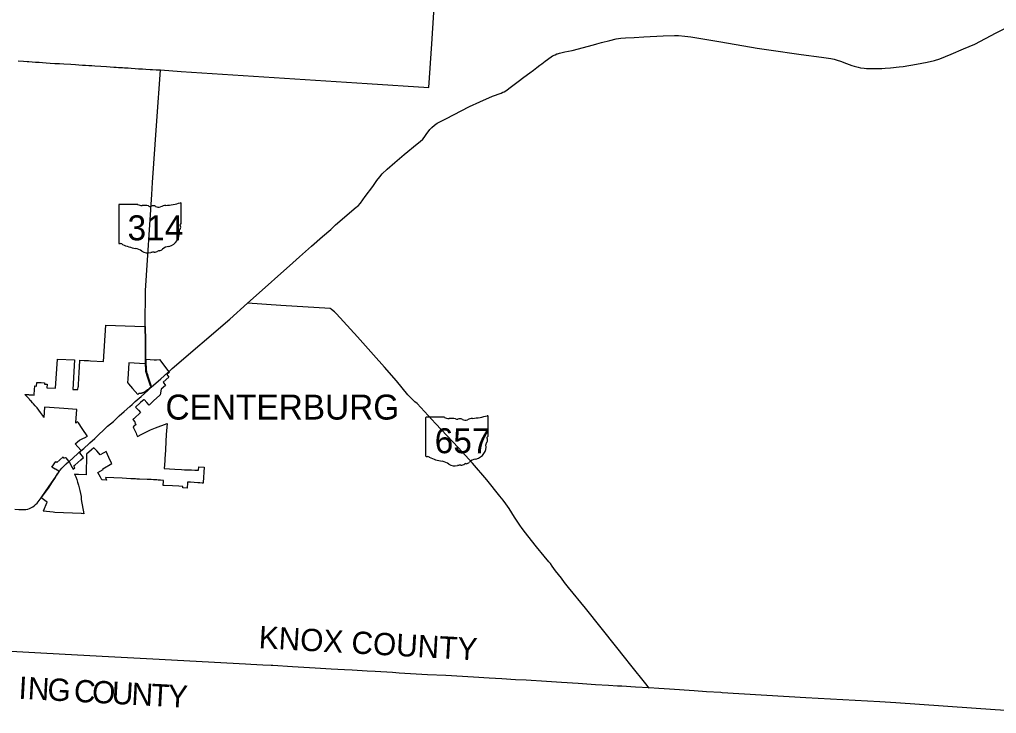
# Model space of a CAD drawing. Extents: x 1851937 to 2123937, y 789467 to 965467.
# Drawn here: x 1909296 to 1953112, y 826095 to 857229 of the extents above; entities that cross this region are included whole.
import ezdxf

# ---------------------------------------------------------------- set-up
doc = ezdxf.new("R2010")
doc.units = 0
for name, color, linetype in [('GM_X_Corporation', 7, 'Continuous'), ('GM_X_Corporation_Text', 7, 'Continuous'), ('GM_X_County', 7, 'Continuous'), ('GM_X_County_Text', 7, 'Continuous'), ('GM_X_State_Location', 7, 'Continuous'), ('GM_X_State_Route', 7, 'Continuous'), ('GM_X_State_Shield', 7, 'Continuous'), ('GM_X_US_Location', 7, 'Continuous'), ('GM_X_US_Route', 7, 'Continuous')]:
    doc.layers.add(name, color=color, linetype=linetype)

msp = doc.modelspace()

# ---------------------------------------------------------------- linework, layer by layer
at = {"layer": 'GM_X_Corporation'}
msp.add_lwpolyline([(1914951, 841986), (1914953, 841784), (1914954, 841776), (1914917, 841779), (1914202, 841823), (1914152, 841092), (1914142, 840939), (1914176, 840882), (1914362, 840675), (1914601, 840409), (1914651, 840452), (1914664, 840462), (1914665, 840463), (1914676, 840463), (1914689, 840463), (1914700, 840463), (1914710, 840463), (1914719, 840464), (1914728, 840464), (1914736, 840465), (1914743, 840467), (1914752, 840469), (1914760, 840471), (1914770, 840474), (1914778, 840477), (1914786, 840479), (1914793, 840482), (1914800, 840485), (1914807, 840488), (1914814, 840491), (1914821, 840494), (1914828, 840496), (1914836, 840497), (1914843, 840498), (1914852, 840500), (1914860, 840502), (1914867, 840504), (1914873, 840507), (1914879, 840509), (1914885, 840512), (1914891, 840515), (1914897, 840518), (1914903, 840521), (1914909, 840525), (1914915, 840530), (1914921, 840534), (1914928, 840539), (1914935, 840544), (1914941, 840548), (1914947, 840552), (1914953, 840555), (1914958, 840559), (1914962, 840562), (1914967, 840566), (1914972, 840570), (1914977, 840575), (1914983, 840580), (1914988, 840585), (1914992, 840590), (1914996, 840594), (1915000, 840598), (1915005, 840601), (1915013, 840607), (1915017, 840609), (1915021, 840612), (1915023, 840616), (1915027, 840620), (1915037, 840627), (1915045, 840631), (1915051, 840633), (1915059, 840633), (1915065, 840633), (1915068, 840633), (1915115, 840675), (1915160, 840716), (1915185, 840738), (1915209, 840760), (1915166, 840898), (1915150, 840948), (1915135, 840994), (1915078, 841176), (1915029, 841332), (1915009, 841396), (1914998, 841441), (1914991, 841478), (1914988, 841520), (1914985, 841602), (1914984, 841617), (1914977, 841775), (1914977, 841984), (1915331, 841967), (1915441, 841961), (1915573, 841981), (1915764, 841726), (1915976, 841444), (1915994, 841420), (1916012, 841396), (1915904, 841300), (1915991, 841191), (1915737, 840957), (1915837, 840814), (1915651, 840646), (1915606, 840395), (1915605, 840394), (1915584, 840375), (1915306, 840116), (1915109, 839931), (1915000, 840050), (1914882, 840178), (1914866, 840164), (1914814, 840118), (1914728, 840044), (1914708, 840025), (1914504, 839842), (1914591, 839745), (1914629, 839704), (1914728, 839594), (1914431, 839334), (1914414, 839319), (1914381, 839290), (1914460, 839185), (1914486, 839150), (1914460, 839126), (1914522, 839058), (1914396, 838950), (1914413, 838914), (1914438, 838857), (1914466, 838796), (1914493, 838736), (1914498, 838725), (1914520, 838676), (1914547, 838616), (1914574, 838556), (1914587, 838526), (1914775, 838623), (1915169, 838827), (1915400, 838912), (1915915, 839102), (1915875, 838607), (1915871, 838557), (1915868, 838507), (1915864, 838403), (1915859, 838303), (1915853, 838163), (1915849, 838063), (1915845, 837963), (1915843, 837938), (1915839, 837863), (1915832, 837763), (1915826, 837664), (1915819, 837564), (1915811, 837444), (1915799, 837256), (1915788, 837079), (1916262, 837054), (1916564, 837038), (1916699, 837031), (1916768, 837029), (1916786, 837028), (1917007, 837021), (1917163, 837017), (1917329, 837012), (1917339, 837164), (1917576, 837147), (1917535, 836462), (1917533, 836434), (1917533, 836432), (1917485, 836435), (1917383, 836442), (1917292, 836447), (1917127, 836459), (1916971, 836469), (1916871, 836475), (1916853, 836476), (1916831, 836477), (1916829, 836448), (1916817, 836208), (1916618, 836219), (1916621, 836279), (1916436, 836289), (1916152, 836306), (1915789, 836327), (1915744, 836329), (1915756, 836518), (1915758, 836548), (1915752, 836549), (1915613, 836558), (1915533, 836564), (1915508, 836566), (1915456, 836570), (1915403, 836573), (1915298, 836581), (1915194, 836588), (1915044, 836599), (1915048, 836587), (1915019, 836588), (1914669, 836608), (1914557, 836614), (1914504, 836617), (1914303, 836628), (1914291, 836628), (1913899, 836648), (1913157, 836686), (1913197, 836559), (1913008, 836577), (1912984, 836579), (1912926, 836697), (1912807, 836903), (1913047, 837039), (1913034, 837077), (1913429, 837312), (1913430, 837312), (1913366, 837448), (1913179, 837844), (1913071, 837788), (1912911, 837704), (1912849, 837772), (1912846, 837775), (1912758, 837872), (1912704, 837931), (1912630, 838012), (1912528, 837926), (1912296, 837729), (1912287, 836796), (1911938, 836816), (1911835, 836822), (1911795, 836824), (1911765, 836826), (1911815, 836708), (1911861, 836588), (1911902, 836467), (1911940, 836344), (1911974, 836221), (1912004, 836096), (1912029, 835971), (1912056, 835826), (1912059, 835697), (1912178, 835057), (1912070, 835062), (1912058, 835062), (1910885, 835116), (1910808, 835120), (1910351, 835165), (1910364, 835194), (1910533, 835569), (1910266, 835764), (1910412, 835962), (1910622, 836252), (1910751, 836449), (1910908, 836687), (1910959, 836766), (1910973, 836788), (1911028, 836873), (1911056, 836917), (1911082, 836955), (1911057, 836969), (1910913, 837051), (1910901, 837059), (1910751, 837144), (1910922, 837400), (1910966, 837353), (1911238, 837601), (1911253, 837608), (1911281, 837556), (1911363, 837580), (1911376, 837563), (1911488, 837416), (1911508, 837389), (1911514, 837394), (1911530, 837365), (1911572, 837292), (1911659, 837135), (1911704, 837055), (1911778, 837121), (1911735, 837203), (1911773, 837237), (1911908, 837357), (1912047, 837482), (1912163, 837584), (1911995, 837783), (1911973, 837808), (1912010, 837841), (1912031, 837860), (1912062, 837887), (1912063, 837888), (1912041, 837913), (1911793, 838188), (1911986, 838361), (1912169, 838449), (1912212, 838469), (1912341, 838531), (1912336, 838538), (1912330, 838546), (1912323, 838558), (1912293, 838602), (1912167, 838789), (1912109, 838876), (1911937, 839131), (1911900, 839186), (1911848, 839144), (1911823, 839124), (1911824, 839146), (1911868, 839737), (1911275, 839775), (1911072, 839788), (1910410, 839832), (1910390, 839375), (1910319, 839486), (1910243, 839595), (1910165, 839701), (1910082, 839804), (1909997, 839905), (1909925, 839983), (1909872, 840038), (1909811, 840103), (1909764, 840159), (1909723, 840208), (1909555, 840388), (1909535, 840409), (1909694, 840399), (1909734, 840397), (1909807, 840392), (1909891, 840387), (1909954, 840383), (1909955, 840403), (1909968, 840620), (1909979, 840791), (1910058, 840782), (1910069, 840950), (1910182, 840943), (1910263, 840938), (1910413, 840929), (1910410, 840875), (1910535, 840867), (1910525, 840708), (1910915, 840684), (1910991, 841994), (1910995, 841994), (1911763, 841956), (1911689, 840637), (1911903, 840625), (1911920, 840756), (1911937, 840755), (1911945, 840878), (1911946, 840938), (1911951, 841035), (1911957, 841134), (1911960, 841193), (1911967, 841324), (1911970, 841384), (1911975, 841479), (1911980, 841559), (1911984, 841639), (1911988, 841719), (1911996, 841856), (1912001, 841945), (1912201, 841935), (1912383, 841926), (1912482, 841921), (1913061, 841893), (1913166, 843522), (1914906, 843461), (1914936, 843460), (1914942, 842809), (1914942, 842763), (1914944, 842613)], close=True, dxfattribs=at)
at = {"layer": 'GM_X_County'}
for points in [[(1909228, 855373), (1909473, 855356), (1909636, 855344), (1909653, 855344), (1909718, 855340), (1909865, 855332), (1910013, 855322), (1910176, 855313), (1910323, 855301), (1910496, 855291), (1910667, 855279), (1910886, 855263), (1911089, 855250), (1911289, 855238), (1911595, 855220), (1911806, 855208), (1911952, 855199), (1912116, 855189), (1912255, 855180), (1912402, 855170), (1912532, 855160), (1912680, 855151), (1912942, 855134), (1913203, 855117), (1913367, 855107), (1913531, 855095), (1913629, 855089), (1913727, 855083), (1913825, 855078), (1913907, 855073), (1914005, 855066), (1914103, 855060), (1914169, 855055), (1914300, 855047), (1914479, 855035), (1914638, 855024), (1914807, 855015), (1914960, 855004), (1915150, 854993), (1915265, 854986), (1915428, 854976), (1915511, 854971), (1915616, 854967), (1916548, 854895), (1922109, 854540), (1924891, 854366), (1927657, 854187), (1927783, 856133), (1927916, 858268)], [(1955665, 826095), (1953053, 826265), (1948592, 826572), (1947877, 826620), (1944569, 826800), (1940804, 827028), (1940744, 827034), (1940112, 827070), (1939560, 827107), (1938444, 827185), (1937968, 827208), (1937532, 827240), (1936924, 827276), (1936311, 827314), (1936120, 827325), (1935716, 827350), (1935132, 827380), (1934356, 827436), (1933609, 827479), (1932937, 827525), (1932012, 827584), (1931539, 827608), (1930920, 827644), (1930354, 827679), (1929657, 827724), (1928412, 827800), (1927588, 827835), (1926322, 827910), (1926021, 827928), (1925241, 827975), (1924884, 827998), (1924212, 828035), (1923869, 828056), (1923280, 828086), (1922550, 828131), (1921535, 828187), (1920653, 828242), (1920580, 828244), (1920206, 828267), (1919668, 828292), (1919433, 828302), (1915271, 828536), (1913287, 828636), (1911340, 828742), (1906703, 828996)]]:
    msp.add_lwpolyline(points, dxfattribs=at)
at = {"layer": 'GM_X_State_Route'}
for p, q in [((1932725, 855249), (1932868, 855355)), ((1932868, 855355), (1932978, 855435)), ((1948747, 855103), (1948926, 855129)), ((1931487, 854316), (1931655, 854442)), ((1931655, 854442), (1931920, 854638)), ((1931920, 854638), (1932176, 854833)), ((1919515, 844497), (1919781, 844733)), ((1915084, 840619), (1915206, 840729)), ((1913760, 839445), (1913993, 839645)), ((1913609, 839299), (1913760, 839445)), ((1910174, 835645), (1910264, 835774)), ((1933258, 832598), (1933182, 832706))]:
    msp.add_line(p, q, dxfattribs=at)
for points in [[(1948926, 855129), (1949519, 855232), (1950001, 855322), (1950336, 855397), (1950569, 855472), (1951083, 855678), (1951641, 855914), (1952137, 856122), (1953099, 856631)], [(1953099, 856631), (1953363, 856770), (1953647, 856909)], [(1935188, 856140), (1935391, 856195), (1935766, 856292), (1936051, 856357), (1936263, 856386), (1936476, 856409), (1936868, 856428), (1937294, 856450), (1938156, 856495), (1938672, 856514)], [(1938672, 856514), (1938848, 856509), (1939133, 856478), (1939405, 856451), (1940034, 856352), (1940754, 856232), (1942385, 855940), (1942903, 855866)], [(1933509, 855720), (1933579, 855741), (1933755, 855780), (1934080, 855839), (1935041, 856101), (1935188, 856140)], [(1942903, 855866), (1944355, 855662), (1945268, 855542), (1945688, 855476), (1945839, 855445), (1945963, 855411), (1946123, 855365)], [(1932978, 855435), (1933199, 855598), (1933312, 855652)], [(1933312, 855652), (1933400, 855687), (1933430, 855697), (1933509, 855720)], [(1946123, 855365), (1946385, 855264), (1946625, 855174), (1946733, 855134), (1946912, 855088)], [(1914937, 843490), (1914940, 845074), (1915228, 849386), (1915265, 849923), (1915382, 851619), (1915455, 852677), (1915617, 854964)], [(1932176, 854833), (1932343, 854958), (1932491, 855070)], [(1932491, 855070), (1932632, 855177), (1932725, 855249)], [(1946912, 855088), (1947014, 855065), (1947175, 855046), (1947279, 855033), (1947529, 855033), (1947974, 855038), (1948114, 855045), (1948362, 855059), (1948747, 855103)], [(1927438, 851934), (1927527, 852070), (1927693, 852290), (1927791, 852390), (1927914, 852493), (1928021, 852573), (1928145, 852643), (1928410, 852781), (1929472, 853332), (1929935, 853532), (1930513, 853784), (1930890, 853932), (1930979, 853969), (1931030, 853990), (1931102, 854026), (1931357, 854218), (1931487, 854316)], [(1925139, 849735), (1925324, 850008), (1925451, 850177), (1925565, 850299), (1925780, 850515), (1926122, 850820), (1926543, 851178), (1927135, 851645), (1927267, 851752), (1927378, 851865), (1927438, 851934)], [(1919781, 844733), (1921554, 846319), (1921848, 846578), (1922394, 847060), (1922886, 847495), (1923254, 847814), (1923469, 848015), (1924394, 848807), (1924478, 848878), (1924582, 848987), (1924795, 849292), (1925139, 849735)], [(1916064, 841501), (1916141, 841573), (1918723, 843786), (1919515, 844497)], [(1926772, 840333), (1926710, 840398), (1926209, 841017), (1925663, 841633), (1925175, 842187), (1924447, 843000), (1923822, 843688), (1923505, 844026), (1923417, 844114), (1923356, 844167), (1923277, 844232), (1923230, 844268), (1921013, 844405), (1919515, 844497)], [(1914937, 843438), (1914937, 843448), (1914937, 843490)], [(1914951, 841794), (1914948, 842220), (1914942, 842813), (1914937, 843438)], [(1915206, 840729), (1915167, 840799), (1915024, 841247), (1914975, 841393), (1914965, 841425), (1914954, 841508), (1914951, 841778), (1914951, 841794)], [(1915206, 840729), (1915631, 841108), (1915948, 841394)], [(1915948, 841394), (1915986, 841429), (1916064, 841501)], [(1913993, 839645), (1914248, 839863), (1914341, 839950), (1914360, 839968), (1914486, 840086), (1914746, 840313), (1915052, 840590), (1915084, 840619)], [(1933182, 832706), (1933107, 832817), (1933042, 832900), (1932826, 833153), (1932489, 833564), (1931926, 834279), (1931804, 834446), (1931759, 834504), (1931496, 834896), (1931260, 835284), (1931106, 835508), (1930990, 835664), (1930841, 835846), (1930258, 836581), (1929617, 837329), (1928988, 838007), (1927950, 839110), (1927124, 839996), (1927029, 840084), (1926772, 840333)], [(1912409, 838196), (1912456, 838238), (1912673, 838437), (1913244, 838979), (1913507, 839200), (1913609, 839299)], [(1911507, 837394), (1911519, 837404), (1911896, 837745), (1911973, 837816)], [(1911973, 837816), (1912032, 837869), (1912052, 837885)], [(1912052, 837885), (1912172, 837986), (1912188, 837999), (1912409, 838196)], [(1911063, 836944), (1911113, 837012), (1911188, 837102), (1911249, 837161), (1911308, 837217), (1911348, 837255), (1911368, 837274), (1911387, 837291), (1911507, 837394)], [(1910264, 835774), (1910621, 836286), (1910904, 836697), (1911001, 836848), (1911006, 836857), (1911048, 836922), (1911063, 836944)], [(1909580, 835242), (1909667, 835261), (1909741, 835288), (1909809, 835322), (1909888, 835364), (1909952, 835408), (1910015, 835468), (1910087, 835538), (1910138, 835593), (1910174, 835645)], [(1909086, 835267), (1909267, 835252), (1909580, 835242)], [(1936429, 828622), (1936084, 829051), (1934685, 830813), (1933918, 831748), (1933736, 831978), (1933598, 832159), (1933474, 832325), (1933340, 832491), (1933258, 832598)], [(1937533, 827237), (1937389, 827423), (1936715, 828266), (1936429, 828622)]]:
    msp.add_lwpolyline(points, dxfattribs=at)
at = {"layer": 'GM_X_State_Shield'}
for p, q in [((1913746, 848905), (1913746, 847204)), ((1914594, 848934), (1913774, 848934)), ((1916548, 848086), (1916548, 848976)), ((1916547, 848087), (1916548, 848086)), ((1927509, 839352), (1927509, 837651)), ((1928357, 839382), (1927537, 839382)), ((1930311, 838534), (1930311, 839424)), ((1930311, 838534), (1930311, 838534))]:
    msp.add_line(p, q, dxfattribs=at)
for centre, major_axis, start_param, end_param in [((1913778, 848908), (32.5, 0), 1.712693, 3.28349), ((1914789, 849132), (315, 0), 4.042523, 4.731795), ((1914894, 847979), (1130, 0), 1.404758, 1.657858), ((1915150, 848917), (90.8, 0), 3.836095, 5.185415), ((1915284, 848721), (189, 0), 0.950623, 2.079405), ((1915527, 848990), (227, 0), 4.081561, 5.145723), ((1915929, 848414), (598, 0), 1.699011, 2.107814), ((1915550, 851253), (2971, 0), 4.814394, 5.042369), ((1916517, 848980), (31.2, 0), 6.141152, 7.989035), ((1916540, 848021), (48.3, 0), 1.883978, 3.671073), ((1916233, 847909), (290, 0), 5.934695, 6.695948), ((1916514, 848083), (33.4, 0), 5.05454, 6.418171), ((1915716, 847601), (743, 0), 5.101752, 6.440018), ((1916659, 847714), (211, 0), 2.387724, 3.262537), ((1913778, 847200), (32.7, 0), 3.00124, 4.508301), ((1913783, 847374), (250, 0), 4.665946, 4.897461), ((1913834, 847105), (90.1, 0), 0.519207, 1.627899), ((1914972, 848634), (2146, 0), 4.195997, 4.488961), ((1916029, 846726), (407, 0), 1.647645, 2.488434), ((1914332, 846439), (671, 0), 0.823519, 1.323587), ((1915058, 847097), (426, 0), 4.026481, 4.996735), ((1915305, 846509), (350, 0), 1.495662, 1.94098), ((1915336, 846970), (227, 0), 4.691044, 5.507374), ((1915541, 846805), (63.9, 0), 1.147584, 2.315152), ((1915514, 847039), (240, 0), 4.937069, 5.64225), ((1927541, 839356), (32.5, 0), 1.712693, 3.28349), ((1928553, 839579), (315, 0), 4.042523, 4.731795), ((1928657, 838427), (1130, 0), 1.404758, 1.657858), ((1928914, 839365), (90.8, 0), 3.836095, 5.185415), ((1929047, 839168), (189, 0), 0.950623, 2.079405), ((1929291, 839438), (227, 0), 4.081561, 5.145723), ((1929692, 838862), (598, 0), 1.699011, 2.107814), ((1929313, 841701), (2971, 0), 4.814394, 5.042369), ((1930280, 839428), (31.2, 0), 6.141152, 7.989035), ((1930423, 838162), (211, 0), 2.387724, 3.262537), ((1930304, 838469), (48.3, 0), 1.883978, 3.671073), ((1929997, 838356), (290, 0), 5.934695, 6.695948), ((1930278, 838531), (33.4, 0), 5.05454, 6.418171), ((1929479, 838048), (743, 0), 5.101752, 6.440018), ((1927542, 837648), (32.7, 0), 3.00124, 4.508301), ((1927546, 837822), (250, 0), 4.665946, 4.897461), ((1927598, 837553), (90.1, 0), 0.519207, 1.627899), ((1928735, 839082), (2146, 0), 4.195997, 4.488961), ((1928096, 836887), (671, 0), 0.823519, 1.323587), ((1929277, 837486), (240, 0), 4.937069, 5.64225), ((1929793, 837174), (407, 0), 1.647645, 2.488434), ((1928822, 837545), (426, 0), 4.026481, 4.996735), ((1929068, 836957), (350, 0), 1.495662, 1.94098), ((1929099, 837417), (227, 0), 4.691044, 5.507374), ((1929304, 837253), (63.9, 0), 1.147584, 2.315152)]:
    msp.add_ellipse(centre, major_axis=major_axis, ratio=0.8, start_param=start_param, end_param=end_param, dxfattribs=at)
at = {"layer": 'GM_X_US_Route'}
for p, q in [((1932725, 855249), (1932868, 855355)), ((1932868, 855355), (1932978, 855435)), ((1948747, 855103), (1948926, 855129)), ((1931487, 854316), (1931655, 854442)), ((1931655, 854442), (1931920, 854638)), ((1931920, 854638), (1932176, 854833)), ((1919515, 844497), (1919781, 844733)), ((1915084, 840619), (1915206, 840729)), ((1913760, 839445), (1913993, 839645)), ((1913609, 839299), (1913760, 839445)), ((1910174, 835645), (1910264, 835774))]:
    msp.add_line(p, q, dxfattribs=at)
for points in [[(1948926, 855129), (1949519, 855232), (1950001, 855322), (1950336, 855397), (1950569, 855472), (1951083, 855678), (1951641, 855914), (1952137, 856122), (1953099, 856631)], [(1953099, 856631), (1953363, 856770), (1953647, 856909)], [(1935188, 856140), (1935391, 856195), (1935766, 856292), (1936051, 856357), (1936263, 856386), (1936476, 856409), (1936868, 856428), (1937294, 856450), (1938156, 856495), (1938672, 856514)], [(1938672, 856514), (1938848, 856509), (1939133, 856478), (1939405, 856451), (1940034, 856352), (1940754, 856232), (1942385, 855940), (1942903, 855866)], [(1933509, 855720), (1933579, 855741), (1933755, 855780), (1934080, 855839), (1935041, 856101), (1935188, 856140)], [(1942903, 855866), (1944355, 855662), (1945268, 855542), (1945688, 855476), (1945839, 855445), (1945963, 855411), (1946123, 855365)], [(1932978, 855435), (1933199, 855598), (1933312, 855652)], [(1933312, 855652), (1933400, 855687), (1933430, 855697), (1933509, 855720)], [(1946123, 855365), (1946385, 855264), (1946625, 855174), (1946733, 855134), (1946912, 855088)], [(1932176, 854833), (1932343, 854958), (1932491, 855070)], [(1932491, 855070), (1932632, 855177), (1932725, 855249)], [(1946912, 855088), (1947014, 855065), (1947175, 855046), (1947279, 855033), (1947529, 855033), (1947974, 855038), (1948114, 855045), (1948362, 855059), (1948747, 855103)], [(1927438, 851934), (1927527, 852070), (1927693, 852290), (1927791, 852390), (1927914, 852493), (1928021, 852573), (1928145, 852643), (1928410, 852781), (1929472, 853332), (1929935, 853532), (1930513, 853784), (1930890, 853932), (1930979, 853969), (1931030, 853990), (1931102, 854026), (1931357, 854218), (1931487, 854316)], [(1925139, 849735), (1925324, 850008), (1925451, 850177), (1925565, 850299), (1925780, 850515), (1926122, 850820), (1926543, 851178), (1927135, 851645), (1927267, 851752), (1927378, 851865), (1927438, 851934)], [(1919781, 844733), (1921554, 846319), (1921848, 846578), (1922394, 847060), (1922886, 847495), (1923254, 847814), (1923469, 848015), (1924394, 848807), (1924478, 848878), (1924582, 848987), (1924795, 849292), (1925139, 849735)], [(1916064, 841501), (1916141, 841573), (1918723, 843786), (1919515, 844497)], [(1915206, 840729), (1915631, 841108), (1915948, 841394)], [(1915948, 841394), (1915986, 841429), (1916064, 841501)], [(1913993, 839645), (1914248, 839863), (1914341, 839950), (1914360, 839968), (1914486, 840086), (1914746, 840313), (1915052, 840590), (1915084, 840619)], [(1912409, 838196), (1912456, 838238), (1912673, 838437), (1913244, 838979), (1913507, 839200), (1913609, 839299)], [(1911507, 837394), (1911519, 837404), (1911896, 837745), (1911973, 837816)], [(1911973, 837816), (1912032, 837869), (1912052, 837885)], [(1912052, 837885), (1912172, 837986), (1912188, 837999), (1912409, 838196)], [(1911063, 836944), (1911113, 837012), (1911188, 837102), (1911249, 837161), (1911308, 837217), (1911348, 837255), (1911368, 837274), (1911387, 837291), (1911507, 837394)], [(1910264, 835774), (1910621, 836286), (1910904, 836697), (1911001, 836848), (1911006, 836857), (1911048, 836922), (1911063, 836944)], [(1909580, 835242), (1909667, 835261), (1909741, 835288), (1909809, 835322), (1909888, 835364), (1909952, 835408), (1910015, 835468), (1910087, 835538), (1910138, 835593), (1910174, 835645)], [(1909086, 835267), (1909267, 835252), (1909580, 835242)]]:
    msp.add_lwpolyline(points, dxfattribs=at)

# ---------------------------------------------------------------- texts
at = {"layer": 'GM_X_Corporation_Text'}
msp.add_text('CENTERBURG', height=1120, rotation=0, dxfattribs=at).set_placement((1915842, 839281))
at = {"layer": 'GM_X_County_Text'}
for s, rotation, p in [('KNOX COUNTY', 356.7703, (1920006, 829027)), ('I', 356.8861, (1909237, 826757)), ('N', 356.8895, (1909645, 826735)), ('G', 356.8885, (1910529, 826687)), ('C', 356.8877, (1911715, 826622)), ('O', 356.8885, (1912528, 826578)), ('U', 356.8885, (1913411, 826530)), ('N', 356.8883, (1914294, 826482)), ('T', 356.8884, (1915177, 826434)), ('Y', 356.8883, (1915924, 826394))]:
    msp.add_text(s, height=1000, rotation=rotation, dxfattribs=at).set_placement(p)
at = {"layer": 'GM_X_State_Location'}
for s, p in [('314', (1914775, 847634)), ('657', (1928538, 838082))]:
    msp.add_text(s, height=1, rotation=0, dxfattribs=at).set_placement(p)
for s, p in [('s', (1915128, 847707)), ('r', (1915128, 847707)), ('s', (1928891, 838155)), ('r', (1928891, 838155))]:
    msp.add_text(s, height=1, dxfattribs=at).set_placement(p)
at = {"layer": 'GM_X_State_Shield'}
for s, p in [('314', (1914141, 847324)), ('657', (1927916, 837771))]:
    msp.add_text(s, height=1120.7, dxfattribs=at).set_placement(p)
at = {"layer": 'GM_X_US_Location'}
for s in ['0', '/']:
    msp.add_text(s, height=1, dxfattribs=at).set_placement((1925876, 850596))

doc.saveas('drawing.dxf')
